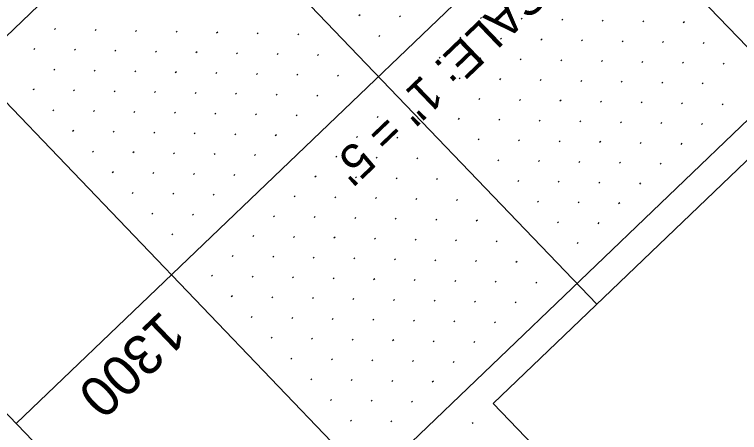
# Model space of a CAD drawing. Extents: x 2148987 to 2151117, y 142806 to 144993.
# Drawn here: x 2149366.7 to 2149493.1, y 143340.3 to 143413.2 of the extents above; entities that cross this region are included whole.
import ezdxf

# ---------------------------------------------------------------- set-up
doc = ezdxf.new("R2010")
doc.units = 0
for name, color, linetype in [('Pr_Abut_ph4', 7, 'Continuous'), ('PR_PIER_PH3', 7, 'Continuous'), ('PR_Road_Asphalt', 7, 'Continuous'), ('PR_Road_Concrete', 7, 'Continuous'), ('SHT_Profile_Grid_Minor', 7, 'Continuous'), ('Wall D Bore', 7, 'Continuous')]:
    doc.layers.add(name, color=color, linetype=linetype)

msp = doc.modelspace()

# ---------------------------------------------------------------- linework, layer by layer
at = {"layer": 'PR_PIER_PH3'}
for p, q in [((2150469.54, 144467.67), (2149332.4, 143377.92)), ((2150504.13, 144431.57), (2149367, 143341.82)), ((2150538.73, 144395.47), (2149401.59, 143305.72)), ((2149258.7, 143653.55), (2149504.33, 143397.25)), ((2149222.6, 143618.96), (2149468.23, 143362.65))]:
    msp.add_line(p, q, dxfattribs=at)
at = {"layer": 'PR_Road_Asphalt'}
msp.add_lwpolyline([(2149643.76, 143468.54), (2149481.31, 143312.87), (2149450.18, 143345.35), (2149612.63, 143501.03)], close=True, dxfattribs=at)
at = {"layer": 'PR_Road_Concrete'}
msp.add_line((2149134.61, 143638.51), (2149463.26, 143295.57), dxfattribs=at)
msp.add_lwpolyline([(2150941.76, 143974.91), (2149804.63, 142885.16), (2149078.13, 143643.25), (2150215.26, 144733)], close=True, dxfattribs=at)
at = {"layer": 'SHT_Profile_Grid_Minor'}
for p, q in [((2149426.95, 143413.13), (2149426.77, 143412.95)), ((2149434.02, 143412.98), (2149433.84, 143412.8)), ((2149448.16, 143412.68), (2149447.98, 143412.5)), ((2149455.23, 143412.53), (2149455.05, 143412.35)), ((2149462.3, 143412.38), (2149462.12, 143412.2)), ((2149469.37, 143412.23), (2149469.19, 143412.05)), ((2149476.44, 143412.07), (2149476.26, 143411.9)), ((2149483.51, 143411.92), (2149483.33, 143411.75)), ((2149373.86, 143410.72), (2149373.68, 143410.55)), ((2149380.93, 143410.57), (2149380.75, 143410.4)), ((2149388, 143410.42), (2149387.82, 143410.25)), ((2149395.07, 143410.27), (2149394.89, 143410.1)), ((2149402.14, 143410.12), (2149401.95, 143409.95)), ((2149409.2, 143409.97), (2149409.02, 143409.8)), ((2149416.27, 143409.82), (2149416.09, 143409.65)), ((2149430.41, 143409.52), (2149430.23, 143409.34)), ((2149444.55, 143409.22), (2149444.37, 143409.04)), ((2149451.62, 143409.07), (2149451.44, 143408.89)), ((2149458.69, 143408.92), (2149458.51, 143408.74)), ((2149465.76, 143408.77), (2149465.58, 143408.59)), ((2149472.83, 143408.62), (2149472.65, 143408.44)), ((2149479.9, 143408.46), (2149479.72, 143408.29)), ((2149486.97, 143408.31), (2149486.79, 143408.14)), ((2149370.25, 143407.26), (2149370.07, 143407.09)), ((2149377.32, 143407.11), (2149377.14, 143406.94)), ((2149384.39, 143406.96), (2149384.21, 143406.79)), ((2149391.46, 143406.81), (2149391.28, 143406.64)), ((2149398.53, 143406.66), (2149398.34, 143406.49)), ((2149405.59, 143406.51), (2149405.41, 143406.34)), ((2149412.66, 143406.36), (2149412.48, 143406.19)), ((2149419.73, 143406.21), (2149419.55, 143406.04)), ((2149440.94, 143405.76), (2149440.76, 143405.58)), ((2149448.01, 143405.61), (2149447.83, 143405.43)), ((2149455.08, 143405.46), (2149454.9, 143405.28)), ((2149462.15, 143405.31), (2149461.97, 143405.13)), ((2149469.22, 143405.16), (2149469.04, 143404.98)), ((2149476.29, 143405.01), (2149476.11, 143404.83)), ((2149483.36, 143404.85), (2149483.18, 143404.68)), ((2149490.43, 143404.7), (2149490.25, 143404.53)), ((2149373.71, 143403.65), (2149373.53, 143403.48)), ((2149380.78, 143403.5), (2149380.6, 143403.33)), ((2149387.85, 143403.35), (2149387.67, 143403.18)), ((2149394.92, 143403.2), (2149394.73, 143403.03)), ((2149401.98, 143403.05), (2149401.8, 143402.88)), ((2149409.05, 143402.9), (2149408.87, 143402.73)), ((2149416.12, 143402.75), (2149415.94, 143402.58)), ((2149423.19, 143402.6), (2149423.01, 143402.43)), ((2149437.33, 143402.3), (2149437.15, 143402.12)), ((2149444.4, 143402.15), (2149444.22, 143401.97)), ((2149451.47, 143402), (2149451.29, 143401.82)), ((2149458.54, 143401.85), (2149458.36, 143401.67)), ((2149465.61, 143401.7), (2149465.43, 143401.52)), ((2149472.68, 143401.55), (2149472.5, 143401.37)), ((2149479.75, 143401.4), (2149479.57, 143401.22)), ((2149370.1, 143400.19), (2149369.92, 143400.02)), ((2149377.17, 143400.04), (2149376.99, 143399.87)), ((2149486.82, 143401.24), (2149486.64, 143401.07)), ((2149384.24, 143399.89), (2149384.06, 143399.72)), ((2149391.31, 143399.74), (2149391.12, 143399.57)), ((2149398.37, 143399.59), (2149398.19, 143399.42)), ((2149405.44, 143399.44), (2149405.26, 143399.27)), ((2149412.51, 143399.29), (2149412.33, 143399.12)), ((2149419.58, 143399.14), (2149419.4, 143398.97)), ((2149440.79, 143398.69), (2149440.61, 143398.51)), ((2149447.86, 143398.54), (2149447.68, 143398.36)), ((2149454.93, 143398.39), (2149454.75, 143398.21)), ((2149462, 143398.24), (2149461.82, 143398.06)), ((2149469.07, 143398.09), (2149468.89, 143397.91)), ((2149476.14, 143397.94), (2149475.96, 143397.76)), ((2149483.21, 143397.79), (2149483.03, 143397.61)), ((2149490.28, 143397.63), (2149490.1, 143397.46)), ((2149373.56, 143396.58), (2149373.38, 143396.41)), ((2149380.63, 143396.43), (2149380.45, 143396.26)), ((2149387.7, 143396.28), (2149387.51, 143396.11)), ((2149394.76, 143396.13), (2149394.58, 143395.96)), ((2149401.83, 143395.98), (2149401.65, 143395.81)), ((2149408.9, 143395.83), (2149408.72, 143395.66)), ((2149415.97, 143395.68), (2149415.79, 143395.51)), ((2149430.11, 143395.38), (2149429.93, 143395.21)), ((2149444.25, 143395.08), (2149444.07, 143394.9)), ((2149451.32, 143394.93), (2149451.14, 143394.75)), ((2149458.39, 143394.78), (2149458.21, 143394.6)), ((2149465.46, 143394.63), (2149465.28, 143394.45)), ((2149472.53, 143394.48), (2149472.35, 143394.3)), ((2149479.6, 143394.33), (2149479.42, 143394.15)), ((2149486.67, 143394.18), (2149486.49, 143394)), ((2149377.02, 143392.97), (2149376.84, 143392.8)), ((2149384.09, 143392.82), (2149383.9, 143392.65)), ((2149391.15, 143392.67), (2149390.97, 143392.5)), ((2149398.22, 143392.52), (2149398.04, 143392.35)), ((2149405.29, 143392.37), (2149405.11, 143392.2)), ((2149412.36, 143392.22), (2149412.18, 143392.05)), ((2149426.5, 143391.92), (2149426.32, 143391.75)), ((2149433.57, 143391.77), (2149433.39, 143391.6)), ((2149447.71, 143391.47), (2149447.53, 143391.3)), ((2149454.78, 143391.32), (2149454.6, 143391.14)), ((2149461.85, 143391.17), (2149461.67, 143390.99)), ((2149468.92, 143391.02), (2149468.74, 143390.84)), ((2149475.99, 143390.87), (2149475.81, 143390.69)), ((2149483.06, 143390.72), (2149482.88, 143390.54)), ((2149380.48, 143389.36), (2149380.3, 143389.19)), ((2149387.54, 143389.21), (2149387.36, 143389.04)), ((2149394.61, 143389.06), (2149394.43, 143388.89)), ((2149401.68, 143388.91), (2149401.5, 143388.74)), ((2149408.75, 143388.76), (2149408.57, 143388.59)), ((2149422.89, 143388.46), (2149422.71, 143388.29)), ((2149429.96, 143388.31), (2149429.78, 143388.14)), ((2149437.03, 143388.16), (2149436.85, 143387.99)), ((2149451.17, 143387.86), (2149450.99, 143387.69)), ((2149458.24, 143387.71), (2149458.06, 143387.53)), ((2149465.31, 143387.56), (2149465.13, 143387.38)), ((2149472.38, 143387.41), (2149472.2, 143387.23)), ((2149479.45, 143387.26), (2149479.27, 143387.08)), ((2149383.94, 143385.75), (2149383.75, 143385.58)), ((2149391, 143385.6), (2149390.82, 143385.43)), ((2149398.07, 143385.45), (2149397.89, 143385.28)), ((2149405.14, 143385.3), (2149404.96, 143385.13)), ((2149419.28, 143385), (2149419.1, 143384.83)), ((2149426.35, 143384.85), (2149426.17, 143384.68)), ((2149433.42, 143384.7), (2149433.24, 143384.53)), ((2149440.49, 143384.55), (2149440.31, 143384.38)), ((2149454.63, 143384.25), (2149454.45, 143384.08)), ((2149461.7, 143384.1), (2149461.52, 143383.92)), ((2149468.77, 143383.95), (2149468.59, 143383.77)), ((2149475.84, 143383.8), (2149475.66, 143383.62)), ((2149387.39, 143382.14), (2149387.21, 143381.97)), ((2149394.46, 143381.99), (2149394.28, 143381.82)), ((2149401.53, 143381.84), (2149401.35, 143381.67)), ((2149415.67, 143381.54), (2149415.49, 143381.37)), ((2149422.74, 143381.39), (2149422.56, 143381.22)), ((2149429.81, 143381.24), (2149429.63, 143381.07)), ((2149436.88, 143381.09), (2149436.7, 143380.92)), ((2149443.95, 143380.94), (2149443.77, 143380.77)), ((2149458.09, 143380.64), (2149457.91, 143380.47)), ((2149465.16, 143380.49), (2149464.98, 143380.31)), ((2149472.23, 143380.34), (2149472.05, 143380.16)), ((2149390.85, 143378.53), (2149390.67, 143378.36)), ((2149397.92, 143378.38), (2149397.74, 143378.21)), ((2149412.06, 143378.08), (2149411.88, 143377.91)), ((2149419.13, 143377.93), (2149418.95, 143377.76)), ((2149426.2, 143377.78), (2149426.02, 143377.61)), ((2149433.27, 143377.63), (2149433.09, 143377.46)), ((2149440.34, 143377.48), (2149440.16, 143377.31)), ((2149447.41, 143377.33), (2149447.23, 143377.16)), ((2149461.55, 143377.03), (2149461.37, 143376.86)), ((2149468.62, 143376.88), (2149468.44, 143376.7)), ((2149394.31, 143374.92), (2149394.13, 143374.75)), ((2149408.45, 143374.62), (2149408.27, 143374.45)), ((2149415.52, 143374.47), (2149415.34, 143374.3)), ((2149422.59, 143374.32), (2149422.41, 143374.15)), ((2149429.66, 143374.17), (2149429.48, 143374)), ((2149436.73, 143374.02), (2149436.55, 143373.85)), ((2149443.8, 143373.87), (2149443.62, 143373.7)), ((2149450.87, 143373.72), (2149450.69, 143373.55)), ((2149465.01, 143373.42), (2149464.83, 143373.25)), ((2149404.84, 143371.16), (2149404.66, 143370.99)), ((2149411.91, 143371.01), (2149411.73, 143370.84)), ((2149418.98, 143370.86), (2149418.8, 143370.69)), ((2149426.05, 143370.71), (2149425.87, 143370.54)), ((2149433.12, 143370.56), (2149432.94, 143370.39)), ((2149440.19, 143370.41), (2149440.01, 143370.24)), ((2149447.26, 143370.26), (2149447.08, 143370.09)), ((2149454.33, 143370.11), (2149454.15, 143369.94)), ((2149401.23, 143367.7), (2149401.05, 143367.53)), ((2149408.3, 143367.55), (2149408.12, 143367.38)), ((2149415.37, 143367.4), (2149415.19, 143367.23)), ((2149422.44, 143367.25), (2149422.26, 143367.08)), ((2149429.51, 143367.1), (2149429.33, 143366.93)), ((2149436.58, 143366.95), (2149436.4, 143366.78)), ((2149443.65, 143366.8), (2149443.47, 143366.63)), ((2149450.72, 143366.65), (2149450.54, 143366.48)), ((2149457.79, 143366.5), (2149457.61, 143366.33)), ((2149404.69, 143364.09), (2149404.51, 143363.92)), ((2149411.76, 143363.94), (2149411.58, 143363.77)), ((2149418.83, 143363.79), (2149418.65, 143363.62)), ((2149425.9, 143363.64), (2149425.72, 143363.47)), ((2149432.97, 143363.49), (2149432.79, 143363.32)), ((2149440.04, 143363.34), (2149439.86, 143363.17)), ((2149447.11, 143363.19), (2149446.93, 143363.02)), ((2149454.18, 143363.04), (2149454, 143362.87)), ((2149408.15, 143360.48), (2149407.97, 143360.31)), ((2149415.22, 143360.33), (2149415.04, 143360.16)), ((2149422.29, 143360.18), (2149422.11, 143360.01)), ((2149429.36, 143360.03), (2149429.18, 143359.86)), ((2149436.43, 143359.88), (2149436.25, 143359.71)), ((2149443.5, 143359.73), (2149443.32, 143359.56)), ((2149450.57, 143359.58), (2149450.39, 143359.41)), ((2149411.61, 143356.87), (2149411.43, 143356.7)), ((2149418.68, 143356.72), (2149418.5, 143356.55)), ((2149425.75, 143356.57), (2149425.57, 143356.4)), ((2149432.82, 143356.42), (2149432.64, 143356.25)), ((2149439.89, 143356.27), (2149439.71, 143356.1)), ((2149446.96, 143356.12), (2149446.78, 143355.95)), ((2149415.07, 143353.26), (2149414.89, 143353.09)), ((2149422.14, 143353.11), (2149421.96, 143352.94)), ((2149429.21, 143352.96), (2149429.03, 143352.79)), ((2149436.28, 143352.81), (2149436.1, 143352.64)), ((2149443.35, 143352.66), (2149443.17, 143352.49)), ((2149418.53, 143349.65), (2149418.35, 143349.48)), ((2149425.6, 143349.5), (2149425.42, 143349.33)), ((2149432.67, 143349.35), (2149432.49, 143349.18)), ((2149439.74, 143349.2), (2149439.56, 143349.03)), ((2149421.99, 143346.04), (2149421.81, 143345.87)), ((2149429.06, 143345.89), (2149428.88, 143345.72)), ((2149436.13, 143345.74), (2149435.95, 143345.57)), ((2149425.45, 143342.43), (2149425.27, 143342.26)), ((2149432.52, 143342.28), (2149432.34, 143342.11)), ((2149446.66, 143341.98), (2149446.48, 143341.81))]:
    msp.add_line(p, q, dxfattribs=at)

# ---------------------------------------------------------------- texts
at = {"layer": 'Pr_Abut_ph4'}
msp.add_text('VERT. SCALE: 1" = 5\'', height=6, rotation=223.7809, dxfattribs=at).set_placement((2149478.76, 143442))
at = {"layer": 'Wall D Bore'}
msp.add_text('1300', height=7, rotation=223.7809, dxfattribs=at).set_placement((2149392.36, 143361.76))

doc.saveas('drawing.dxf')
